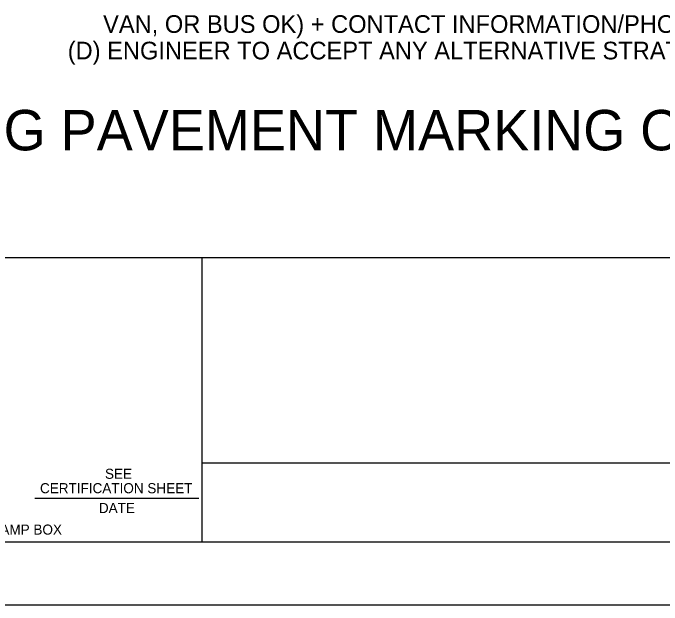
# Model space of a CAD drawing. Extents: x 0 to 17, y 0 to 11.
# Drawn here: x 12.372 to 14.941, y 0 to 2.343 of the extents above; entities that cross this region are included whole.
import ezdxf

# ---------------------------------------------------------------- set-up
doc = ezdxf.new("R2010")
doc.units = 0
for name, color, linetype in [('SH_GI_PlotLimits', 7, 'Continuous'), ('SH_GI_SheetBorder1', 7, 'Continuous'), ('SH_GI_SheetBorder2', 7, 'Continuous'), ('SH_GI_SheetBorder3', 7, 'Continuous'), ('SH_GI_SheetTextInCells', 7, 'Continuous'), ('TR_WZ_WorkZoneTextCurrent', 7, 'Continuous')]:
    doc.layers.add(name, color=color, linetype=linetype)

msp = doc.modelspace()

# ---------------------------------------------------------------- linework, layer by layer
at = {"layer": 'SH_GI_PlotLimits'}
msp.add_lwpolyline([(0, 11), (17, 11), (17, 0), (0, 0)], close=True, dxfattribs=at)
at = {"layer": 'SH_GI_SheetBorder1'}
msp.add_line((12.4584, 0.4233), (13.1083, 0.4233), dxfattribs=at)
at = {"layer": 'SH_GI_SheetBorder2'}
msp.add_line((13.12, 0.5625), (16.24, 0.5625), dxfattribs=at)
at = {"layer": 'SH_GI_SheetBorder3'}
for p, q in [((1, 1.375), (16.75, 1.375)), ((13.12, 1.3759), (13.12, 0.25)), ((1, 0.25), (16.75, 0.25))]:
    msp.add_line(p, q, dxfattribs=at)

# ---------------------------------------------------------------- texts
at = {"layer": 'SH_GI_SheetTextInCells'}
for s, p in [('SEE', (12.7366, 0.4995)), ('CERTIFICATION SHEET', (12.4793, 0.4425)), ('DATE', (12.7123, 0.3641)), ('STAMP BOX', (12.2541, 0.2786))]:
    msp.add_text(s, height=0.04, dxfattribs=at).set_placement(p)
at = {"layer": 'TR_WZ_WorkZoneTextCurrent'}
for s, height, p in [('VAN, OR BUS OK) + CONTACT INFORMATION/PHONE BOX/LABORER. ', 0.07, (12.729, 2.2647)), ('(D) ENGINEER TO ACCEPT ANY ALTERNATIVE STRATEGIES.', 0.07, (12.589, 2.1597)), ('FREEWAY (2+ LANES): MOBILE SINGLE RIGHT LANE CLOSURE, EXCLUDING PAVEMENT MARKING OPERATIONS', 0.16, (4.6606, 1.7997))]:
    msp.add_text(s, height=height, rotation=360, dxfattribs=at).set_placement(p)

doc.saveas('drawing.dxf')
